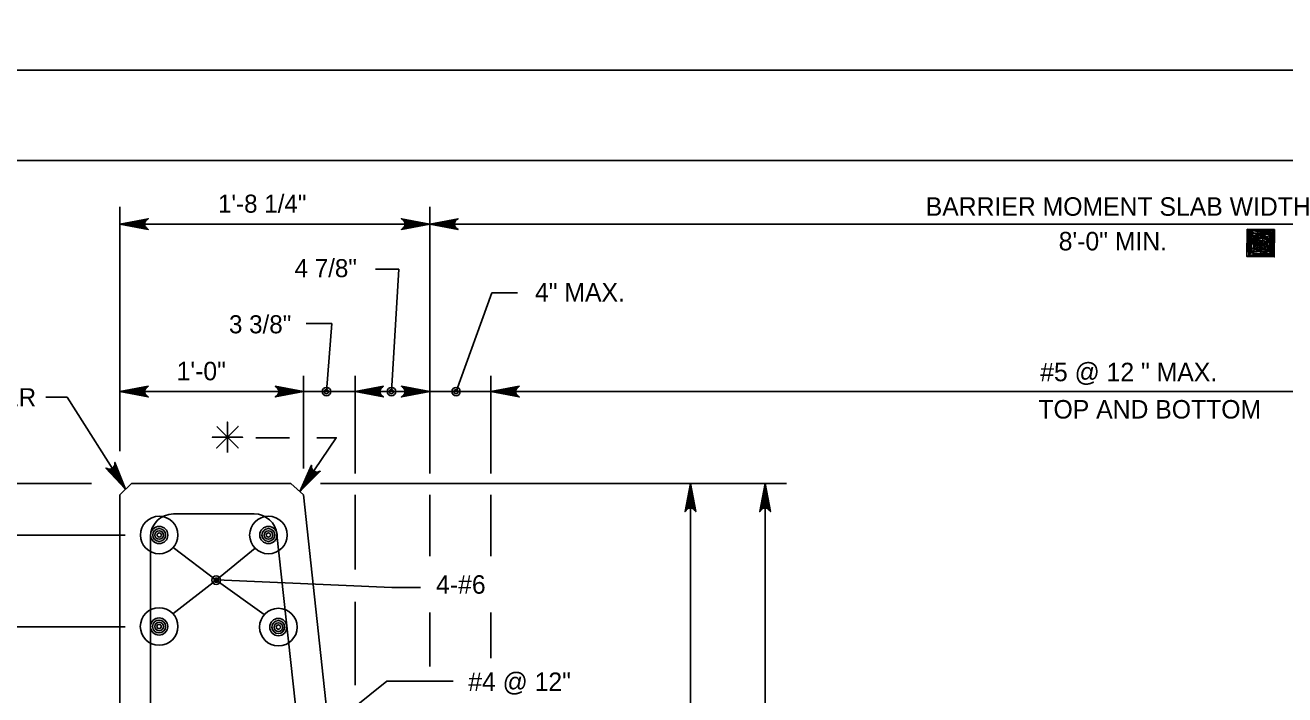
# Model space of a CAD drawing. Extents: x 638167 to 640248, y 296544 to 298920.
# Drawn here: x 638272.3 to 638481.4, y 298222.8 to 298334 of the extents above; entities that cross this region are included whole.
import ezdxf

# ---------------------------------------------------------------- set-up
doc = ezdxf.new("R2010")
doc.units = 0
for name, color, linetype in [('1', 7, 'Continuous'), ('50', 7, 'Continuous'), ('57', 7, 'Continuous'), ('PLT-BNDY', 7, 'Continuous')]:
    doc.layers.add(name, color=color, linetype=linetype)

# ---------------------------------------------------------------- blocks, each defined once
blk = doc.blocks.new('BAR')
at = {"layer": '50'}
for radius in [2, 1.5, 1, 0.5]:
    blk.add_circle((0, 0), radius, dxfattribs=at)
blk = doc.blocks.new('DIMDOT')
at = {"layer": '57'}
for radius in [2, 1]:
    blk.add_circle((0, 0), radius, dxfattribs=at)

msp = doc.modelspace()

# ---------------------------------------------------------------- linework, layer by layer
at = {"layer": '1'}
for p, q in [((638991.78, 298311.48), (638205.78, 298311.48)), ((638288.02, 298263.26), (638288.02, 298303.81)), ((638339.46, 298259.53), (638339.46, 298303.81)), ((638288.02, 298300.95), (638583.3, 298300.95)), ((638477.39, 298297.8), (638477.39, 298297.8)), ((638334.34, 298293.46), (638330.45, 298293.46)), ((638333.1, 298273.13), (638334.34, 298293.46)), ((638343.82, 298273.13), (638349.77, 298289.53)), ((638349.77, 298289.53), (638354.03, 298289.53)), ((638323.2, 298284.44), (638318.95, 298284.44)), ((638322.31, 298273.13), (638323.2, 298284.44)), ((638318.5, 298260.38), (638318.5, 298275.76)), ((638327.07, 298259.53), (638327.07, 298275.76)), ((638349.62, 298259.53), (638349.62, 298275.76)), ((638288.02, 298273.13), (638596.12, 298273.13)), ((638275.72, 298272.2), (638279.3, 298272.2)), ((638279.3, 298272.2), (638288.97, 298256.94)), ((638305.87, 298265.56), (638305.87, 298265.56)), ((638218.88, 298257.9), (638283.32, 298257.9)), ((638288.02, 298255.99), (638289.93, 298257.9)), ((638289.93, 298257.9), (638316.4, 298257.9)), ((638316.4, 298257.9), (638318.5, 298256)), ((638321.31, 298257.9), (638398.69, 298257.9)), ((638382.72, 298144.15), (638382.72, 298257.9)), ((638395.12, 298151.22), (638395.12, 298257.9)), ((638288.02, 298158.2), (638288.02, 298255.99)), ((638318.5, 298256), (638326.39, 298182.99)), ((638327.07, 298243.59), (638327.07, 298256)), ((638339.46, 298245.83), (638339.46, 298256)), ((638349.62, 298245.83), (638349.62, 298256)), ((638296.91, 298252.82), (638310.32, 298252.82)), ((638242.51, 298249.32), (638288.9, 298249.32)), ((638293.1, 298187.28), (638293.1, 298249.01)), ((638314.1, 298249.41), (638323.15, 298165.59)), ((638304.01, 298241.82), (638296.86, 298247.22)), ((638304.04, 298241.85), (638310.47, 298247.12)), ((638304.01, 298241.82), (638296.83, 298236.23)), ((638304.01, 298241.82), (638311.99, 298236.1)), ((638333.17, 298240.58), (638304.04, 298241.85)), ((638333.17, 298240.58), (638337.94, 298240.58)), ((638327.07, 298224.38), (638327.07, 298238.23)), ((638339.46, 298227.51), (638339.46, 298236.44)), ((638349.62, 298228.85), (638349.62, 298236.44)), ((638242.51, 298234.08), (638288.9, 298234.08)), ((638332.33, 298225.03), (638317.98, 298213.54)), ((638332.33, 298225.03), (638343.33, 298225.03))]:
    msp.add_line(p, q, dxfattribs=at)
for points in [[(638288.02, 298300.95), (638292.72, 298301.83), (638292.54, 298301.7), (638292.36, 298301.58), (638292.26, 298301.42), (638292.17, 298301.26), (638292.14, 298301.1), (638292.12, 298300.95), (638292.14, 298300.79), (638292.17, 298300.63), (638292.26, 298300.47), (638292.36, 298300.32), (638292.54, 298300.19), (638292.72, 298300.06), (638288.02, 298300.95), (638292.54, 298300.19), (638292.36, 298300.32), (638288.02, 298300.95), (638292.26, 298300.47), (638292.17, 298300.63), (638288.02, 298300.95), (638292.14, 298300.79), (638292.12, 298300.95), (638288.02, 298300.95), (638292.14, 298301.1), (638292.17, 298301.26), (638288.02, 298300.95), (638292.26, 298301.42), (638292.36, 298301.58), (638288.02, 298300.95), (638292.54, 298301.7)], [(638339.46, 298300.95), (638334.76, 298300.06), (638334.94, 298300.19), (638335.12, 298300.32), (638335.21, 298300.47), (638335.31, 298300.63), (638335.33, 298300.79), (638335.36, 298300.95), (638335.33, 298301.1), (638335.31, 298301.26), (638335.21, 298301.42), (638335.12, 298301.58), (638334.94, 298301.7), (638334.76, 298301.83), (638339.46, 298300.95), (638334.94, 298301.7), (638335.12, 298301.58), (638339.46, 298300.95), (638335.21, 298301.42), (638335.31, 298301.26), (638339.46, 298300.95), (638335.33, 298301.1), (638335.36, 298300.95), (638339.46, 298300.95), (638335.33, 298300.79), (638335.31, 298300.63), (638339.46, 298300.95), (638335.21, 298300.47), (638335.12, 298300.32), (638339.46, 298300.95), (638334.94, 298300.19)], [(638339.46, 298300.95), (638344.15, 298301.83), (638343.97, 298301.7), (638343.79, 298301.58), (638343.7, 298301.42), (638343.61, 298301.26), (638343.58, 298301.1), (638343.55, 298300.95), (638343.58, 298300.79), (638343.61, 298300.63), (638343.7, 298300.47), (638343.79, 298300.32), (638343.97, 298300.19), (638344.15, 298300.06), (638339.46, 298300.95), (638343.97, 298300.19), (638343.79, 298300.32), (638339.46, 298300.95), (638343.7, 298300.47), (638343.61, 298300.63), (638339.46, 298300.95), (638343.58, 298300.79), (638343.55, 298300.95), (638339.46, 298300.95), (638343.58, 298301.1), (638343.61, 298301.26), (638339.46, 298300.95), (638343.7, 298301.42), (638343.79, 298301.58), (638339.46, 298300.95), (638343.97, 298301.7)], [(638475.15, 298300.09), (638475.1, 298295.56), (638479.63, 298295.51), (638479.67, 298300.04), (638475.15, 298300.09), (638475.4, 298295.85), (638479.35, 298295.69), (638479.45, 298299.82), (638475.48, 298299.77), (638475.65, 298296.16), (638479.11, 298296), (638479.2, 298299.45), (638475.72, 298299.45), (638475.93, 298296.43), (638478.89, 298296.34), (638478.89, 298299.2), (638476.06, 298299.05), (638476.28, 298296.71), (638478.56, 298296.62), (638478.58, 298298.9), (638476.36, 298298.74), (638476.59, 298297.07), (638478.22, 298296.9), (638478.33, 298298.53), (638476.61, 298298.61), (638476.75, 298297.35), (638477.98, 298297.27), (638477.99, 298298.14), (638477.13, 298298.33), (638477.06, 298297.59), (638477.67, 298297.52), (638477.74, 298297.89), (638477.43, 298297.9), (638475.36, 298299.95), (638479.55, 298299.85), (638475.25, 298295.64), (638479.29, 298295.87), (638475.42, 298299.77), (638479.19, 298298.4), (638475.53, 298299.09), (638479.09, 298297.08), (638475.49, 298298.01), (638478.99, 298296.43), (638475.66, 298297.02), (638478.74, 298296), (638476.12, 298296), (638476.89, 298299.69), (638477.41, 298296.05), (638477.88, 298299.62), (638479.07, 298295.9), (638479.39, 298299.63), (638478.03, 298296.59), (638475.29, 298299.83), (638475.59, 298295.91), (638476.21, 298299.08), (638479.14, 298299.57), (638475.85, 298299.82)], [(638288.02, 298273.13), (638292.72, 298274.02), (638292.54, 298273.89), (638292.36, 298273.76), (638292.26, 298273.61), (638292.17, 298273.45), (638292.14, 298273.29), (638292.12, 298273.13), (638292.14, 298272.98), (638292.17, 298272.82), (638292.26, 298272.66), (638292.36, 298272.5), (638292.54, 298272.38), (638292.72, 298272.25), (638288.02, 298273.13), (638292.54, 298272.38), (638292.36, 298272.5), (638288.02, 298273.13), (638292.26, 298272.66), (638292.17, 298272.82), (638288.02, 298273.13), (638292.14, 298272.98), (638292.12, 298273.13), (638288.02, 298273.13), (638292.14, 298273.29), (638292.17, 298273.45), (638288.02, 298273.13), (638292.26, 298273.61), (638292.36, 298273.76), (638288.02, 298273.13), (638292.54, 298273.89)], [(638318.5, 298273.13), (638313.8, 298272.25), (638313.99, 298272.38), (638314.17, 298272.5), (638314.26, 298272.66), (638314.35, 298272.82), (638314.38, 298272.98), (638314.41, 298273.13), (638314.38, 298273.29), (638314.35, 298273.45), (638314.26, 298273.61), (638314.17, 298273.76), (638313.99, 298273.89), (638313.8, 298274.02), (638318.5, 298273.13), (638313.99, 298273.89), (638314.17, 298273.76), (638318.5, 298273.13), (638314.26, 298273.61), (638314.35, 298273.45), (638318.5, 298273.13), (638314.38, 298273.29), (638314.41, 298273.13), (638318.5, 298273.13), (638314.38, 298272.98), (638314.35, 298272.82), (638318.5, 298273.13), (638314.26, 298272.66), (638314.17, 298272.5), (638318.5, 298273.13), (638313.99, 298272.38)], [(638327.07, 298273.13), (638331.77, 298274.02), (638331.59, 298273.89), (638331.41, 298273.76), (638331.32, 298273.61), (638331.22, 298273.45), (638331.2, 298273.29), (638331.17, 298273.13), (638331.2, 298272.98), (638331.22, 298272.82), (638331.32, 298272.66), (638331.41, 298272.5), (638331.59, 298272.38), (638331.77, 298272.25), (638327.07, 298273.13), (638331.59, 298272.38), (638331.41, 298272.5), (638327.07, 298273.13), (638331.32, 298272.66), (638331.22, 298272.82), (638327.07, 298273.13), (638331.2, 298272.98), (638331.17, 298273.13), (638327.07, 298273.13), (638331.2, 298273.29), (638331.22, 298273.45), (638327.07, 298273.13), (638331.32, 298273.61), (638331.41, 298273.76), (638327.07, 298273.13), (638331.59, 298273.89)], [(638339.46, 298273.13), (638334.76, 298272.25), (638334.94, 298272.38), (638335.12, 298272.5), (638335.21, 298272.66), (638335.31, 298272.82), (638335.33, 298272.98), (638335.36, 298273.13), (638335.33, 298273.29), (638335.31, 298273.45), (638335.21, 298273.61), (638335.12, 298273.76), (638334.94, 298273.89), (638334.76, 298274.02), (638339.46, 298273.13), (638334.94, 298273.89), (638335.12, 298273.76), (638339.46, 298273.13), (638335.21, 298273.61), (638335.31, 298273.45), (638339.46, 298273.13), (638335.33, 298273.29), (638335.36, 298273.13), (638339.46, 298273.13), (638335.33, 298272.98), (638335.31, 298272.82), (638339.46, 298273.13), (638335.21, 298272.66), (638335.12, 298272.5), (638339.46, 298273.13), (638334.94, 298272.38)], [(638349.62, 298273.13), (638354.31, 298274.02), (638354.13, 298273.89), (638353.95, 298273.76), (638353.86, 298273.61), (638353.77, 298273.45), (638353.74, 298273.29), (638353.71, 298273.13), (638353.74, 298272.98), (638353.77, 298272.82), (638353.86, 298272.66), (638353.95, 298272.5), (638354.13, 298272.38), (638354.31, 298272.25), (638349.62, 298273.13), (638354.13, 298272.38), (638353.95, 298272.5), (638349.62, 298273.13), (638353.86, 298272.66), (638353.77, 298272.82), (638349.62, 298273.13), (638353.74, 298272.98), (638353.71, 298273.13), (638349.62, 298273.13), (638353.74, 298273.29), (638353.77, 298273.45), (638349.62, 298273.13), (638353.86, 298273.61), (638353.95, 298273.76), (638349.62, 298273.13), (638354.13, 298273.89)], [(638304.09, 298267.34), (638307.65, 298263.78), (638305.87, 298265.56), (638307.65, 298267.34), (638304.09, 298263.78), (638305.87, 298265.56), (638303.35, 298265.56), (638308.39, 298265.56), (638305.87, 298265.56), (638305.87, 298268.08), (638305.87, 298263.04)], [(638310.61, 298265.48), (638316.16, 298265.48)], [(638320.69, 298265.48), (638323.95, 298265.48), (638317.91, 298256.53)], [(638288.97, 298256.94), (638285.71, 298260.44), (638285.92, 298260.35), (638286.12, 298260.27), (638286.3, 298260.27), (638286.49, 298260.28), (638286.63, 298260.34), (638286.78, 298260.4), (638286.9, 298260.51), (638287.02, 298260.62), (638287.1, 298260.78), (638287.18, 298260.94), (638287.19, 298261.16), (638287.2, 298261.38), (638288.97, 298256.94), (638287.19, 298261.16), (638287.18, 298260.94), (638288.97, 298256.94), (638287.1, 298260.78), (638287.02, 298260.62), (638288.97, 298256.94), (638286.9, 298260.51), (638286.78, 298260.4), (638288.97, 298256.94), (638286.63, 298260.34), (638286.49, 298260.28), (638288.97, 298256.94), (638286.3, 298260.27), (638286.12, 298260.27), (638288.97, 298256.94), (638285.92, 298260.35)], [(638317.91, 298256.53), (638319.83, 298260.91), (638319.83, 298260.69), (638319.83, 298260.47), (638319.91, 298260.31), (638319.99, 298260.14), (638320.1, 298260.03), (638320.22, 298259.92), (638320.36, 298259.85), (638320.51, 298259.79), (638320.69, 298259.77), (638320.87, 298259.76), (638321.08, 298259.84), (638321.28, 298259.92), (638317.91, 298256.53), (638321.08, 298259.84), (638320.87, 298259.76), (638317.91, 298256.53), (638320.69, 298259.77), (638320.51, 298259.79), (638317.91, 298256.53), (638320.36, 298259.85), (638320.22, 298259.92), (638317.91, 298256.53), (638320.1, 298260.03), (638319.99, 298260.14), (638317.91, 298256.53), (638319.91, 298260.31), (638319.83, 298260.47), (638317.91, 298256.53), (638319.83, 298260.69)], [(638382.72, 298257.9), (638383.6, 298253.2), (638383.48, 298253.38), (638383.35, 298253.56), (638383.2, 298253.65), (638383.04, 298253.75), (638382.88, 298253.77), (638382.72, 298253.8), (638382.57, 298253.77), (638382.41, 298253.75), (638382.25, 298253.65), (638382.09, 298253.56), (638381.97, 298253.38), (638381.84, 298253.2), (638382.72, 298257.9), (638381.97, 298253.38), (638382.09, 298253.56), (638382.72, 298257.9), (638382.25, 298253.65), (638382.41, 298253.75), (638382.72, 298257.9), (638382.57, 298253.77), (638382.72, 298253.8), (638382.72, 298257.9), (638382.88, 298253.77), (638383.04, 298253.75), (638382.72, 298257.9), (638383.2, 298253.65), (638383.35, 298253.56), (638382.72, 298257.9), (638383.48, 298253.38)], [(638395.12, 298257.9), (638396, 298253.2), (638395.87, 298253.38), (638395.75, 298253.56), (638395.59, 298253.65), (638395.43, 298253.75), (638395.28, 298253.77), (638395.12, 298253.8), (638394.96, 298253.77), (638394.8, 298253.75), (638394.65, 298253.65), (638394.49, 298253.56), (638394.36, 298253.38), (638394.24, 298253.2), (638395.12, 298257.9), (638394.36, 298253.38), (638394.49, 298253.56), (638395.12, 298257.9), (638394.65, 298253.65), (638394.8, 298253.75), (638395.12, 298257.9), (638394.96, 298253.77), (638395.12, 298253.8), (638395.12, 298257.9), (638395.28, 298253.77), (638395.43, 298253.75), (638395.12, 298257.9), (638395.59, 298253.65), (638395.75, 298253.56), (638395.12, 298257.9), (638395.87, 298253.38)]]:
    msp.add_lwpolyline(points, dxfattribs=at)
for centre in [(638294.55, 298249.32), (638312.68, 298249.32), (638294.53, 298234.13), (638314.33, 298234.03)]:
    msp.add_circle(centre, 3.12, dxfattribs=at)
for centre, start, end in [((638296.91, 298249.01), 90, 180), ((638310.32, 298249.01), 6.1633, 90)]:
    msp.add_arc(centre, 3.81, start, end, dxfattribs=at)
at = {"layer": 'PLT-BNDY'}
for points in [[(638166.78, 298920.48), (639007.78, 298920.48), (639007.78, 298326.48), (638166.78, 298326.48)], [(638166.78, 298326.48), (639007.78, 298326.48), (639007.78, 297732.48), (638166.78, 297732.48)]]:
    msp.add_lwpolyline(points, close=True, dxfattribs=at)

# ---------------------------------------------------------------- block references
at = {"layer": '1', "xscale": 0.349999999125, "yscale": 0.349999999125}
for p in [(638322.31, 298273.13), (638333.1, 298273.13), (638343.82, 298273.13), (638304.01, 298241.82)]:
    msp.add_blockref('DIMDOT', p, dxfattribs=at)
at = {"layer": '1', "xscale": 0.714376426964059, "yscale": 0.714376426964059, "rotation": -90.00000000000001}
for p in [(638294.55, 298249.32), (638312.68, 298249.32), (638294.53, 298234.13), (638314.33, 298234.03)]:
    msp.add_blockref('BAR', p, dxfattribs=at)

# ---------------------------------------------------------------- texts
at = {"layer": '1'}
for s, height, p in [('1\'-8 1/4"', 3, (638304.31, 298302.84)), ('BARRIER MOMENT SLAB WIDTH', 3.072, (638421.78, 298302.33)), ('8\'-0" MIN.', 3.072, (638443.85, 298296.58)), ('4 7/8"', 3, (638317.02, 298292.13)), ('4" MAX.', 3.072, (638356.92, 298288.09)), ('3 3/8"', 3, (638306.13, 298282.81)), ('1\'-0"', 3.072, (638297.44, 298275.01)), ('#5 @ 12 " MAX.', 3.072, (638440.78, 298274.85)), ('CHAMFER', 3, (638254.28, 298270.7)), ('TOP AND BOTTOM', 3.072, (638440.48, 298268.66)), ('4-#6', 3.072, (638340.51, 298239.57)), ('#4 @ 12"', 3.072, (638345.84, 298223.42))]:
    msp.add_text(s, height=height, dxfattribs=at).set_placement(p)

doc.saveas('drawing.dxf')
